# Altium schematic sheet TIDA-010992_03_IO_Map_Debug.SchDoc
size 431 x 279 mm; Date: Not shown in title block; ApprovedBy: Not shown in title block; CheckedBy: Not shown in title block; Author: Not shown in title block; CompanyName: Not shown in title block; Engineer: Not shown in title block; Organization: Not shown in title block; Address1: Not shown in title block; Address2: Not shown in title block; Address3: Not shown in title block; Address4: Not shown in title block; DocumentNumber: 3; Revision: Use project parameter SCH_Rev; SheetNumber: 3; SheetTotal: 13; PageSetup: Record=PageOptions¦CenterHorizontal=True¦CenterVertical=True¦PrintScale=1.00¦XCorrection=1.00¦YCorrection=1.00¦PrintKind=0¦BorderSize=5000000¦LeftOffset=0¦BottomOffset=0¦Orientation=2¦PaperLength=1000¦PaperWidth=1000¦Scale=100¦PaperSource=15¦PrintQuality=600¦MediaType=1¦DitherType=10¦PaperKind=Letter¦PrintScaleMode=1
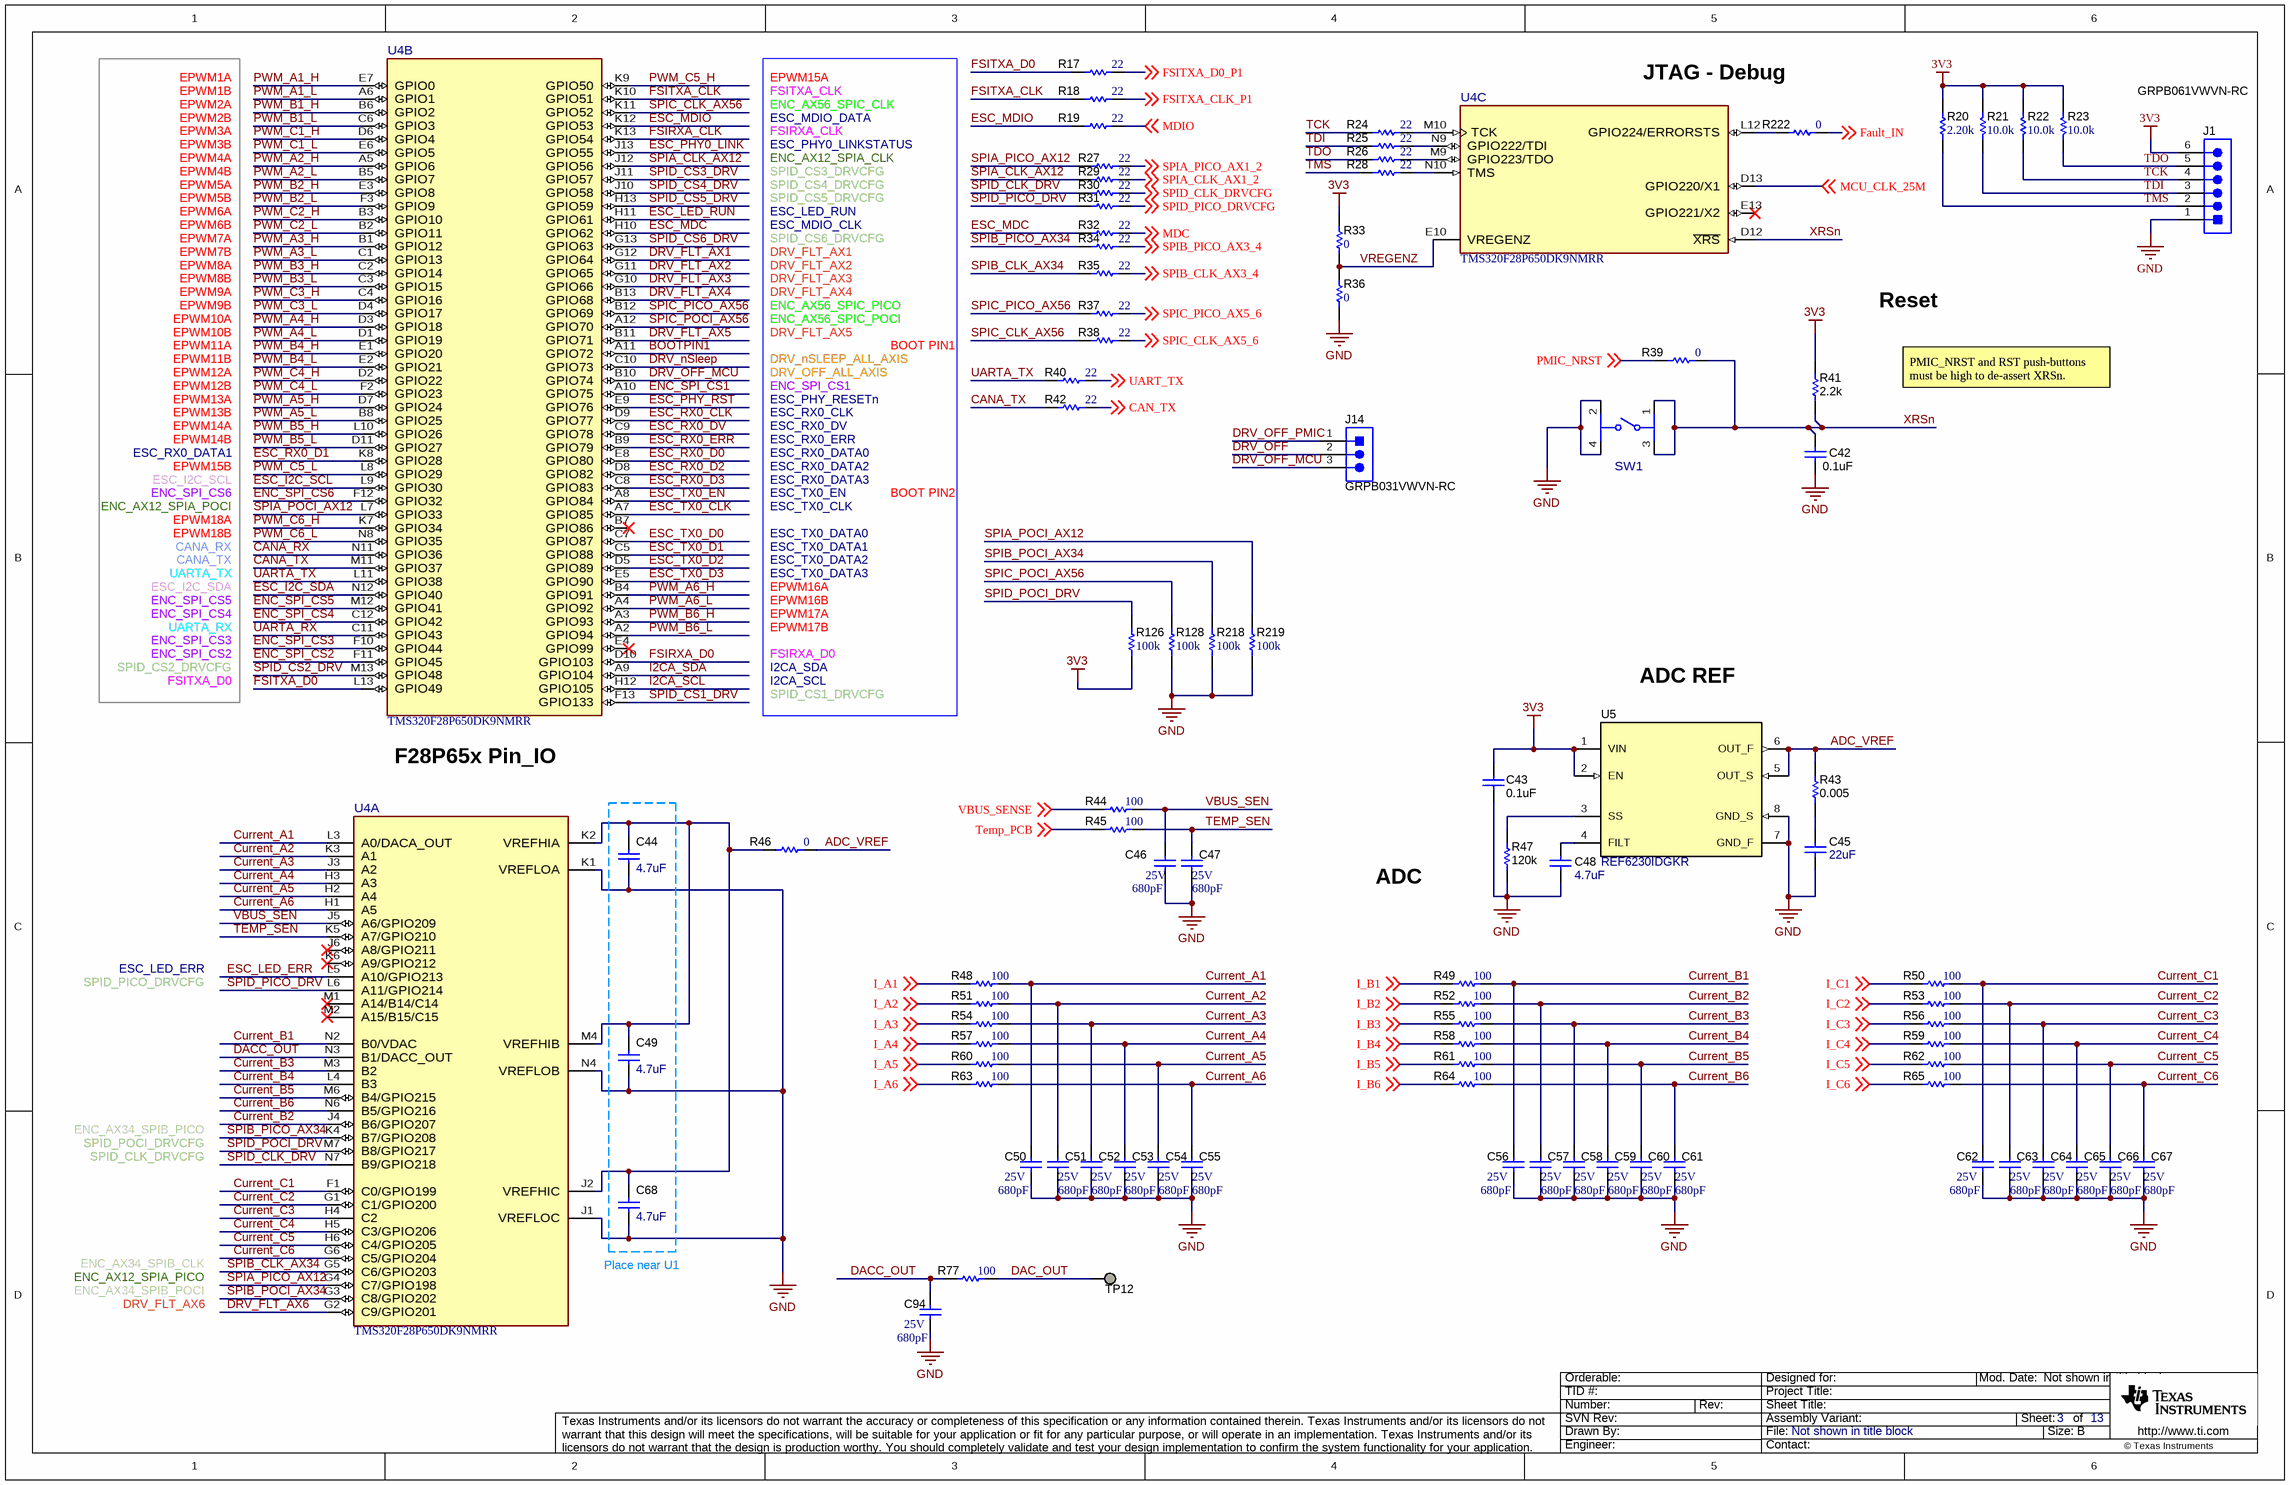
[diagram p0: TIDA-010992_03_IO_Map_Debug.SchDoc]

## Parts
C42  ValueDisplayed: 0.1uF  [0402]  (hidden comment: 885012205037)
C43  ValueDisplayed: 0.1uF  [0402]  (hidden comment: 885012205037)
C44  ValueDisplayed: 4.7uF  [0603]  (hidden comment: GRM188R61C475KAAJ)
C45  ValueDisplayed: 22uF  [0603]  (hidden comment: GRM188R61A226ME15D)
C46  VDC_V: 25V  ValueDisplayed: 680pF  [0201]  (hidden comment: GRM033R71E681KA01D)
C47  VDC_V: 25V  ValueDisplayed: 680pF  [0201]  (hidden comment: GRM033R71E681KA01D)
C48  ValueDisplayed: 4.7uF  [0603]  (hidden comment: GRM188R61C475KAAJ)
C49  ValueDisplayed: 4.7uF  [0603]  (hidden comment: GRM188R61C475KAAJ)
C50  VDC_V: 25V  ValueDisplayed: 680pF  [0201]  (hidden comment: GRM033R71E681KA01D)
C51  VDC_V: 25V  ValueDisplayed: 680pF  [0201]  (hidden comment: GRM033R71E681KA01D)
C52  VDC_V: 25V  ValueDisplayed: 680pF  [0201]  (hidden comment: GRM033R71E681KA01D)
C53  VDC_V: 25V  ValueDisplayed: 680pF  [0201]  (hidden comment: GRM033R71E681KA01D)
C54  VDC_V: 25V  ValueDisplayed: 680pF  [0201]  (hidden comment: GRM033R71E681KA01D)
C55  VDC_V: 25V  ValueDisplayed: 680pF  [0201]  (hidden comment: GRM033R71E681KA01D)
C56  VDC_V: 25V  ValueDisplayed: 680pF  [0201]  (hidden comment: GRM033R71E681KA01D)
C57  VDC_V: 25V  ValueDisplayed: 680pF  [0201]  (hidden comment: GRM033R71E681KA01D)
C58  VDC_V: 25V  ValueDisplayed: 680pF  [0201]  (hidden comment: GRM033R71E681KA01D)
C59  VDC_V: 25V  ValueDisplayed: 680pF  [0201]  (hidden comment: GRM033R71E681KA01D)
C60  VDC_V: 25V  ValueDisplayed: 680pF  [0201]  (hidden comment: GRM033R71E681KA01D)
C61  VDC_V: 25V  ValueDisplayed: 680pF  [0201]  (hidden comment: GRM033R71E681KA01D)
C62  VDC_V: 25V  ValueDisplayed: 680pF  [0201]  (hidden comment: GRM033R71E681KA01D)
C63  VDC_V: 25V  ValueDisplayed: 680pF  [0201]  (hidden comment: GRM033R71E681KA01D)
C64  VDC_V: 25V  ValueDisplayed: 680pF  [0201]  (hidden comment: GRM033R71E681KA01D)
C65  VDC_V: 25V  ValueDisplayed: 680pF  [0201]  (hidden comment: GRM033R71E681KA01D)
C66  VDC_V: 25V  ValueDisplayed: 680pF  [0201]  (hidden comment: GRM033R71E681KA01D)
C67  VDC_V: 25V  ValueDisplayed: 680pF  [0201]  (hidden comment: GRM033R71E681KA01D)
C68  ValueDisplayed: 4.7uF  [0603]  (hidden comment: GRM188R61C475KAAJ)
C94  VDC_V: 25V  ValueDisplayed: 680pF  [0201]  (hidden comment: GRM033R71E681KA01D)
J1  GRPB061VWVN-RC  [Sullins_GRPB061VWVN-RC]
J14  GRPB031VWVN-RC  [Sullins_GRPB031VWVN-RC]
R17  ValueDisplayed: 22  [0201]  (hidden comment: ERJ-1GNJ220C)
R18  ValueDisplayed: 22  [0201]  (hidden comment: ERJ-1GNJ220C)
R19  ValueDisplayed: 22  [0201]  (hidden comment: ERJ-1GNJ220C)
R20  ValueDisplayed: 2.20k  [0402]  (hidden comment: CRCW04022K20FKED)
R21  ValueDisplayed: 10.0k  [0402]  (hidden comment: ERJ-2RKF1002X)
R22  ValueDisplayed: 10.0k  [0402]  (hidden comment: ERJ-2RKF1002X)
R23  ValueDisplayed: 10.0k  [0402]  (hidden comment: ERJ-2RKF1002X)
R24  ValueDisplayed: 22  [0201]  (hidden comment: ERJ-1GNJ220C)
R25  ValueDisplayed: 22  [0201]  (hidden comment: ERJ-1GNJ220C)
R26  ValueDisplayed: 22  [0201]  (hidden comment: ERJ-1GNJ220C)
R27  ValueDisplayed: 22  [0201]  (hidden comment: ERJ-1GNJ220C)
R28  ValueDisplayed: 22  [0201]  (hidden comment: ERJ-1GNJ220C)
R29  ValueDisplayed: 22  [0201]  (hidden comment: ERJ-1GNJ220C)
R30  ValueDisplayed: 22  [0201]  (hidden comment: ERJ-1GNJ220C)
R31  ValueDisplayed: 22  [0201]  (hidden comment: ERJ-1GNJ220C)
R32  ValueDisplayed: 22  [0201]  (hidden comment: ERJ-1GNJ220C)
R33  value 0  [0402L]  (hidden comment: ERJ-2GE0R00X)
R34  ValueDisplayed: 22  [0201]  (hidden comment: ERJ-1GNJ220C)
R35  ValueDisplayed: 22  [0201]  (hidden comment: ERJ-1GNJ220C)
R36  value 0  [0402L]  (hidden comment: ERJ-2GE0R00X)
R37  ValueDisplayed: 22  [0201]  (hidden comment: ERJ-1GNJ220C)
R38  ValueDisplayed: 22  [0201]  (hidden comment: ERJ-1GNJ220C)
R39  value 0  [0402L]  (hidden comment: ERJ-2GE0R00X)
R40  ValueDisplayed: 22  [0201]  (hidden comment: ERJ-1GNJ220C)
R41  ValueDisplayed: 2.2k  [0402]  (hidden comment: CRCW04022K20JNED)
R42  ValueDisplayed: 22  [0201]  (hidden comment: ERJ-1GNJ220C)
R43  ValueDisplayed: 0.005  [0603]  (hidden comment: ERJ3LWFR005V)
R44  ValueDisplayed: 100  [0201]  (hidden comment: RC0201FR-7D100RL)
R45  ValueDisplayed: 100  [0201]  (hidden comment: RC0201FR-7D100RL)
R46  value 0  [0402L]  (hidden comment: ERJ-2GE0R00X)
R47  ValueDisplayed: 120k  [0603]  (hidden comment: RG1608P-124-B-T5)
R48  ValueDisplayed: 100  [0201]  (hidden comment: RC0201FR-7D100RL)
R49  ValueDisplayed: 100  [0201]  (hidden comment: RC0201FR-7D100RL)
R50  ValueDisplayed: 100  [0201]  (hidden comment: RC0201FR-7D100RL)
R51  ValueDisplayed: 100  [0201]  (hidden comment: RC0201FR-7D100RL)
R52  ValueDisplayed: 100  [0201]  (hidden comment: RC0201FR-7D100RL)
R53  ValueDisplayed: 100  [0201]  (hidden comment: RC0201FR-7D100RL)
R54  ValueDisplayed: 100  [0201]  (hidden comment: RC0201FR-7D100RL)
R55  ValueDisplayed: 100  [0201]  (hidden comment: RC0201FR-7D100RL)
R56  ValueDisplayed: 100  [0201]  (hidden comment: RC0201FR-7D100RL)
R57  ValueDisplayed: 100  [0201]  (hidden comment: RC0201FR-7D100RL)
R58  ValueDisplayed: 100  [0201]  (hidden comment: RC0201FR-7D100RL)
R59  ValueDisplayed: 100  [0201]  (hidden comment: RC0201FR-7D100RL)
R60  ValueDisplayed: 100  [0201]  (hidden comment: RC0201FR-7D100RL)
R61  ValueDisplayed: 100  [0201]  (hidden comment: RC0201FR-7D100RL)
R62  ValueDisplayed: 100  [0201]  (hidden comment: RC0201FR-7D100RL)
R63  ValueDisplayed: 100  [0201]  (hidden comment: RC0201FR-7D100RL)
R64  ValueDisplayed: 100  [0201]  (hidden comment: RC0201FR-7D100RL)
R65  ValueDisplayed: 100  [0201]  (hidden comment: RC0201FR-7D100RL)
R77  ValueDisplayed: 100  [0201]  (hidden comment: RC0201FR-7D100RL)
R126  ValueDisplayed: 100k  [0201]  (hidden comment: RC0201FR-07100KL)
R128  ValueDisplayed: 100k  [0201]  (hidden comment: RC0201FR-07100KL)
R218  ValueDisplayed: 100k  [0201]  (hidden comment: RC0201FR-07100KL)
R219  ValueDisplayed: 100k  [0201]  (hidden comment: RC0201FR-07100KL)
R222  value 0  [0402L]  (hidden comment: ERJ-2GE0R00X)
SW1  434351045816  [FP-434351045816_SMT_SW_4MM7_4MM5-MFG]  (value not drawn)
TP12  TESTPOINT  [TP_25MIL-SMT]  (value not drawn)  (no BOM)
U4  TMS320F28P650DK9NMRR  [NMR0169A-MFG]  (parts A,B,C of 4)
U5  REF6230IDGKR  [DGK0008A_N]

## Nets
3V3: C43.1 J1.6 R20.2 R21.1 R22.1 R23.1 R33.2 R41.2 R126.1 U5.1(VIN) U5.2(EN)
GND: C42.2 C43.2 C44.2 C45.2 C46.2 C47.2 C48.2 C49.2 C50.2 C51.2 C52.2 C53.2 C54.2 C55.2 C56.2 C57.2 C58.2 C59.2 C60.2 C61.2 C62.2 C63.2 C64.2 C65.2 C66.2 C67.2 C68.2 C94.2 J1.1 R36.1 R47.1 R128.1 R218.1 R219.1 SW1.2 SW1.4 U4.J1(VREFLOC) U4.K1(VREFLOA) U4.N4(VREFLOB) U5.7(GND_F) U5.8(GND_S)
ADC_VREF: R43.2 R46.2 U5.5(OUT_S) U5.6(OUT_F)
BOOTPIN1: U4.A11(GPIO72)
CAN_TX: R42.2 ; off-sheet CAN_TX
CANA_RX: U4.N11(GPIO36)
CANA_TX: R42.1 U4.M11(GPIO37)
Current_A1: C50.1 R48.2 U4.L3(A0/DACA_OUT)
Current_A2: C51.1 R51.2 U4.K3(A1)
Current_A3: C52.1 R54.2 U4.J3(A2)
Current_A4: C53.1 R57.2 U4.H3(A3)
Current_A5: C54.1 R60.2 U4.H2(A4)
Current_A6: C55.1 R63.2 U4.H1(A5)
Current_B1: C56.1 R49.2 U4.N2(B0/VDAC)
Current_B2: C57.1 R52.2 U4.J4(B6/GPIO207)
Current_B3: C58.1 R55.2 U4.M3(B2)
Current_B4: C59.1 R58.2 U4.L4(B3)
Current_B5: C60.1 R61.2 U4.M6(B4/GPIO215)
Current_B6: C61.1 R64.2 U4.N6(B5/GPIO216)
Current_C1: C62.1 R50.2 U4.F1(C0/GPIO199)
Current_C2: C63.1 R53.2 U4.G1(C1/GPIO200)
Current_C3: C64.1 R56.2 U4.H4(C2)
Current_C4: C65.1 R59.2 U4.H5(C3/GPIO206)
Current_C5: C66.1 R62.2 U4.H6(C4/GPIO205)
Current_C6: C67.1 R65.2 U4.G6(C5/GPIO204)
DAC_OUT: R77.2 TP12.1
DACC_OUT: C94.1 R77.1 U4.N3(B1/DACC_OUT)
DRV_FLT_AX1: U4.G12(GPIO64)
DRV_FLT_AX2: U4.G11(GPIO65)
DRV_FLT_AX3: U4.G10(GPIO66)
DRV_FLT_AX4: U4.B13(GPIO68)
DRV_FLT_AX5: U4.B11(GPIO71)
DRV_FLT_AX6: U4.G2(C9/GPIO201)
DRV_nSleep: U4.C10(GPIO73)
DRV_OFF: J14.2
DRV_OFF_MCU: J14.3 U4.B10(GPIO74)
DRV_OFF_PMIC: J14.1
ENC_SPI_CS1: U4.A10(GPIO75)
ENC_SPI_CS2: U4.F11(GPIO45)
ENC_SPI_CS3: U4.F10(GPIO44)
ENC_SPI_CS4: U4.C12(GPIO42)
ENC_SPI_CS5: U4.M12(GPIO41)
ENC_SPI_CS6: U4.F12(GPIO32)
ESC_I2C_SCL: U4.L9(GPIO30)
ESC_I2C_SDA: U4.N12(GPIO40)
ESC_LED_ERR: U4.L5(A10/GPIO213)
ESC_LED_RUN: U4.H11(GPIO61)
ESC_MDC: R32.1 U4.H10(GPIO62)
ESC_MDIO: R19.1 U4.K12(GPIO53)
ESC_PHY0_LINK: U4.J13(GPIO55)
ESC_PHY_RST: U4.E9(GPIO76)
ESC_RX0_CLK: U4.D9(GPIO77)
ESC_RX0_D0: U4.E8(GPIO80)
ESC_RX0_D1: U4.K8(GPIO28)
ESC_RX0_D2: U4.D8(GPIO82)
ESC_RX0_D3: U4.C8(GPIO83)
ESC_RX0_DV: U4.C9(GPIO78)
ESC_RX0_ERR: U4.B9(GPIO79)
ESC_TX0_CLK: U4.A7(GPIO85)
ESC_TX0_D0: U4.C7(GPIO87)
ESC_TX0_D1: U4.C5(GPIO88)
ESC_TX0_D2: U4.D5(GPIO89)
ESC_TX0_D3: U4.E5(GPIO90)
ESC_TX0_EN: U4.A8(GPIO84)
Fault_IN: R222.2 ; off-sheet Fault_IN
FSIRXA_CLK: U4.K13(GPIO54)
FSIRXA_D0: U4.D10(GPIO103)
FSITXA_CLK: R18.1 U4.K10(GPIO51)
FSITXA_CLK_P1: R18.2 ; off-sheet FSITXA_CLK_P1
FSITXA_D0: R17.1 U4.L13(GPIO49)
FSITXA_D0_P1: R17.2 ; off-sheet FSITXA_D0_P1
I2CA_SCL: U4.H12(GPIO105)
I2CA_SDA: U4.A9(GPIO104)
I_A1: R48.1 ; off-sheet I_A1
I_A2: R51.1 ; off-sheet I_A2
I_A3: R54.1 ; off-sheet I_A3
I_A4: R57.1 ; off-sheet I_A4
I_A5: R60.1 ; off-sheet I_A5
I_A6: R63.1 ; off-sheet I_A6
I_B1: R49.1 ; off-sheet I_B1
I_B2: R52.1 ; off-sheet I_B2
I_B3: R55.1 ; off-sheet I_B3
I_B4: R58.1 ; off-sheet I_B4
I_B5: R61.1 ; off-sheet I_B5
I_B6: R64.1 ; off-sheet I_B6
I_C1: R50.1 ; off-sheet I_C1
I_C2: R53.1 ; off-sheet I_C2
I_C3: R56.1 ; off-sheet I_C3
I_C4: R59.1 ; off-sheet I_C4
I_C5: R62.1 ; off-sheet I_C5
I_C6: R65.1 ; off-sheet I_C6
MCU_CLK_25M: U4.D13(GPIO220/X1) ; off-sheet MCU_CLK_25M
MDC: R32.2 ; off-sheet MDC
MDIO: R19.2 ; off-sheet MDIO
PMIC_NRST: R39.1 ; off-sheet PMIC_NRST
PWM_A1_H: U4.E7(GPIO0)
PWM_A1_L: U4.A6(GPIO1)
PWM_A2_H: U4.A5(GPIO6)
PWM_A2_L: U4.B5(GPIO7)
PWM_A3_H: U4.B1(GPIO12)
PWM_A3_L: U4.C1(GPIO13)
PWM_A4_H: U4.D3(GPIO18)
PWM_A4_L: U4.D1(GPIO19)
PWM_A5_H: U4.D7(GPIO24)
PWM_A5_L: U4.B8(GPIO25)
PWM_A6_H: U4.B4(GPIO91)
PWM_A6_L: U4.A4(GPIO92)
PWM_B1_H: U4.B6(GPIO2)
PWM_B1_L: U4.C6(GPIO3)
PWM_B2_H: U4.E3(GPIO8)
PWM_B2_L: U4.F3(GPIO9)
PWM_B3_H: U4.C2(GPIO14)
PWM_B3_L: U4.C3(GPIO15)
PWM_B4_H: U4.E1(GPIO20)
PWM_B4_L: U4.E2(GPIO21)
PWM_B5_H: U4.L10(GPIO26)
PWM_B5_L: U4.D11(GPIO27)
PWM_B6_H: U4.A3(GPIO93)
PWM_B6_L: U4.A2(GPIO94)
PWM_C1_H: U4.D6(GPIO4)
PWM_C1_L: U4.E6(GPIO5)
PWM_C2_H: U4.B3(GPIO10)
PWM_C2_L: U4.B2(GPIO11)
PWM_C3_H: U4.C4(GPIO16)
PWM_C3_L: U4.D4(GPIO17)
PWM_C4_H: U4.D2(GPIO22)
PWM_C4_L: U4.F2(GPIO23)
PWM_C5_H: U4.K9(GPIO50)
PWM_C5_L: U4.L8(GPIO29)
PWM_C6_H: U4.K7(GPIO34)
PWM_C6_L: U4.N8(GPIO35)
SPIA_CLK_AX1_2: R29.2 ; off-sheet SPIA_CLK_AX1_2
SPIA_CLK_AX12: R29.1 U4.J12(GPIO56)
SPIA_PICO_AX1_2: R27.2 ; off-sheet SPIA_PICO_AX1_2
SPIA_PICO_AX12: R27.1 U4.G4(C7/GPIO198)
SPIA_POCI_AX12: R219.2 U4.L7(GPIO33)
SPIB_CLK_AX3_4: R35.2 ; off-sheet SPIB_CLK_AX3_4
SPIB_CLK_AX34: R35.1 U4.G5(C6/GPIO203)
SPIB_PICO_AX3_4: R34.2 ; off-sheet SPIB_PICO_AX3_4
SPIB_PICO_AX34: R34.1 U4.K4(B7/GPIO208)
SPIB_POCI_AX34: R218.2 U4.G3(C8/GPIO202)
SPIC_CLK_AX5_6: R38.2 ; off-sheet SPIC_CLK_AX5_6
SPIC_CLK_AX56: R38.1 U4.K11(GPIO52)
SPIC_PICO_AX5_6: R37.2 ; off-sheet SPIC_PICO_AX5_6
SPIC_PICO_AX56: R37.1 U4.B12(GPIO69)
SPIC_POCI_AX56: R128.2 U4.A12(GPIO70)
SPID_CLK_DRV: R30.1 U4.N7(B9/GPIO218)
SPID_CLK_DRVCFG: R30.2 ; off-sheet SPID_CLK_DRVCFG
SPID_CS1_DRV: U4.F13(GPIO133)
SPID_CS2_DRV: U4.M13(GPIO48)
SPID_CS3_DRV: U4.J11(GPIO57)
SPID_CS4_DRV: U4.J10(GPIO58)
SPID_CS5_DRV: U4.H13(GPIO59)
SPID_CS6_DRV: U4.G13(GPIO63)
SPID_PICO_DRV: R31.1 U4.L6(A11/GPIO214)
SPID_PICO_DRVCFG: R31.2 ; off-sheet SPID_PICO_DRVCFG
SPID_POCI_DRV: R126.2 U4.M7(B8/GPIO217)
TCK: J1.4 R22.2 R24.1
TDI: J1.3 R21.2 R25.1
TDO: J1.5 R23.2 R26.1
Temp_PCB: R45.1 ; off-sheet Temp_PCB
TEMP_SEN: C47.1 R45.2 U4.K5(A7/GPIO210)
TMS: J1.2 R20.1 R28.1
UART_TX: R40.2 ; off-sheet UART_TX
UARTA_RX: U4.C11(GPIO43)
UARTA_TX: R40.1 U4.L11(GPIO38)
VBUS_SEN: C46.1 R44.2 U4.J5(A6/GPIO209)
VBUS_SENSE: R44.1 ; off-sheet VBUS_SENSE
VREGENZ: R33.1 R36.2 U4.E10(VREGENZ)
XRSn: C42.1 R39.2 R41.1 SW1.1 SW1.3 U4.D12(~{XRS})
NetC44_1: C44.1 C49.1 C68.1 R46.1 U4.J2(VREFHIC) U4.K2(VREFHIA) U4.M4(VREFHIB)
NetC45_1: C45.1 R43.1
NetC48_1: C48.1 U5.4(FILT)
NetR24_2: R24.2 U4.M10(TCK)
NetR25_2: R25.2 U4.N9(GPIO222/TDI)
NetR26_2: R26.2 U4.M9(GPIO223/TDO)
NetR28_2: R28.2 U4.N10(TMS)
NetR47_2: R47.2 U5.3(SS)
NetR222_1: R222.1 U4.L12(GPIO224/ERRORSTS)

Not connected (* = marked no-connect by the designer): U4 B7(GPIO86)* E4(GPIO99)* E13(GPIO221/X2)* J6(A8/GPIO211)* K6(A9/GPIO212)* M1(A14/B14/C14)* M2(A15/B15/C15)*

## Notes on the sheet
- EPWM1A
- EPWM1B
- FSITXA_CLK
- EPWM15A
- JTAG - Debug
- EPWM4A
- EPWM2A
- EPWM2B
- EPWM3A
- EPWM3B
- FSIRXA_CLK
- ESC_MDIO_DATA
- ESC_PHY0_LINKSTATUS
- ENC_AX56_SPIC_CLK
- ENC_AX12_SPIA_CLK
- EPWM5A
- EPWM5B
- EPWM4B
- EPWM6A
- EPWM6B
- ESC_LED_RUN
- ESC_MDIO_CLK
- SPID_CS3_DRVCFG
- SPID_CS5_DRVCFG
- SPID_CS4_DRVCFG
- EPWM7A
- EPWM7B
- EPWM8A
- EPWM8B
- EPWM9A
- SPID_CS6_DRVCFG
- DRV_FLT_AX1
- DRV_FLT_AX2
- DRV_FLT_AX3
- DRV_FLT_AX4
- Reset
- EPWM9B
- EPWM10A
- EPWM10B
- EPWM11A
- EPWM11B
- ENC_AX56_SPIC_PICO
- ENC_AX56_SPIC_POCI
- DRV_FLT_AX5
- DRV_nSLEEP_ALL_AXIS
- BOOT PIN1
- EPWM12A
- EPWM12B
- EPWM13A
- EPWM13B
- EPWM14A
- ESC_PHY_RESETn
- ESC_RX0_CLK
- ESC_RX0_DV
- ENC_SPI_CS1
- DRV_OFF_ALL_AXIS
- PMIC_NRST and RST push-buttons must be high to de-assert XRSn.
- ESC_RX0_DATA1
- EPWM14B
- EPWM15B
- ENC_SPI_CS6
- ESC_I2C_SCL
- ESC_RX0_DATA0
- ESC_RX0_DATA2
- ESC_RX0_DATA3
- ESC_RX0_ERR
- ESC_TX0_EN
- BOOT PIN2
- ENC_AX12_SPIA_POCI
- CANA_RX
- CANA_TX
- EPWM18A
- EPWM18B
- ESC_TX0_CLK
- ESC_TX0_DATA0
- ESC_TX0_DATA1
- ESC_TX0_DATA2
- UARTA_RX
- UARTA_TX
- ENC_SPI_CS4
- ENC_SPI_CS5
- ESC_I2C_SDA
- ESC_TX0_DATA3
- EPWM16A
- EPWM16B
- EPWM17A
- EPWM17B
- FSITXA_D0
- ENC_SPI_CS2
- SPID_CS2_DRVCFG
- ENC_SPI_CS3
- I2CA_SCL
- FSIRXA_D0
- SPID_CS1_DRVCFG
- I2CA_SDA
- ADC REF
- (near U4) F28P65x Pin_IO
- ADC
- ESC_LED_ERR
- SPID_PICO_DRVCFG
- ENC_AX34_SPIB_PICO
- SPID_CLK_DRVCFG
- SPID_POCI_DRVCFG
- ENC_AX12_SPIA_PICO
- ENC_AX34_SPIB_CLK
- ENC_AX34_SPIB_POCI
- Place near U1
- DRV_FLT_AX6

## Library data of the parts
C42 C43 = CMP-0006228-2: CAP, CERM, 0.1 uF, 16 V, +/- 10%, X7R, 0402; Manufacturer: Wurth Elektronik; TaMin_C: -55°C; Polarized: N; SizeAreaWB_mm2: 3; Value1: Unknown; U/M: EA; Value: 0.1uF; TaMax_C: 125°C; SizeZ_mm: 0.6; SizeX_mm: 1; SizeY_mm: 0.5; Value2: 16V; Cap_F: 100nF; AEC Category: Q200
C44 C48 C49 C68 = CMP-0007341-4: CAP, CERM, 4.7 uF, 16 V, +/- 10%, X5R, 0603; Manufacturer: MuRata; TaMin_C: -55°C; Polarized: N; SizeAreaWB_mm2: 4.68; Value1: Unknown; U/M: EA; Value: 4.7uF; TaMax_C: 85°C; SizeZ_mm: 1; SizeX_mm: 1.6; SizeY_mm: 0.8; Value2: 16V; SizeArea_mm2: 1.28; Cap_F: 4.7µF; AEC Category: Q200
C45 = CMP-0007324-5: CAP, CERM, 22 uF, 10 V, +/- 20%, X5R, 0603; Manufacturer: MuRata; TaMin_C: -55°C; Polarized: N; SizeAreaWB_mm2: 4.68; Value1: Unknown; U/M: EA; Value: 22uF; TaMax_C: 85°C; SizeZ_mm: 1; SizeX_mm: 1.6; SizeY_mm: 0.8; Value2: 10V; SizeArea_mm2: 1.28; Cap_F: 22µF; AEC Category: Q200
C46 C47 C50-C67 C94 = CMP-0009776-1: CAP, CERM, 680 pF, 25 V, +/- 10%, X7R, 0201; Manufacturer: MuRata; TaMin_C: -55°C; Polarized: N; SizeAreaWB_mm2: 2.08; Value1: Unknown; U/M: EA; Value: 680pF; TaMax_C: 125°C; SizeZ_mm: 0.26; SizeX_mm: 0.6; SizeY_mm: 0.3; SizeArea_mm2: 0.18; AEC Category: Q200
J1 = CMP-0054561-1: Header, 50mil, 6x1, Gold,  TH; Manufacturer: Sullins Connector Solutions; CT: FALSE; CNHeader: TRUE
J14 = CMP-0054564-1: Header, 50mil, 3x1, Gold, TH; Manufacturer: Sullins Connector Solutions; CNHeader: TRUE; Green_Lifecycle: Not Set; Shrouded: N; Gender: Male; Green_REACh: Incomplete; Row_Count: 1; CT: FALSE
R17-R19 R24-R32 R34 R35 R37 R38 R40 R42 = CMP-0027015-3: RES, 22, 5%, 0.05 W, AEC-Q200 Grade 1, 0201; Manufacturer: Panasonic; Power_W: 50mW; TempCo: 200 ppm/C; Value_Code: 22R0; U/M: EA; Value: 22; EIA_Code: E24; SizeX_mm: 0.6; SizeY_mm: 0.3; SizeZ_mm: 0.26; Value2: 0.05W; SizeArea_mm2: 0.18; AEC Qualified: Y; AEC Grade: 1; AEC Category: Q200
R20 = CMP-0026231-2: RES, 2.20 k, 1%, 0.063 W, AEC-Q200 Grade 0, 0402; Manufacturer: Vishay-Dale; Power_W: 63mW; TempCo: 100 ppm/C; Value_Code: 2k20; Value: 2.20k; Res_ohm: 2.2k; SizeX_mm: 1; SizeY_mm: 0.5; SizeZ_mm: 0.6; Value2: 0.063W; AEC Qualified: Y; AEC Category: Q200; AEC Grade: 0
R21-R23 = CMP-0026658-1: RES, 10.0 k, 1%, 0.1 W, 0402; Manufacturer: Panasonic; Power_W: 100mW; TempCo: 100 ppm/C; Value_Code: 10k0; U/M: EA; Value: 10.0k; EIA_Code: E96; Res_ohm: 10k; SizeX_mm: 1; SizeY_mm: 0.5; SizeZ_mm: 0.6; Value2: 0.1W; VDC_V: 50V; AEC Category: Q200
R33 R36 R39 R46 R222 = CMP-0026992-3: RES, 0, 5%, 0.1 W, AEC-Q200 Grade 0, 0402; Manufacturer: Panasonic; Power_W: 100mW; TempCo: 600 ppm/C; Value_Code: 0000; EIA_Code: E24; SizeX_mm: 1; SizeY_mm: 0.5; SizeZ_mm: 0.6; Value2: 0.1W; AEC Qualified: Y; VDC_V: 50V; AEC Category: Q200; SizeAreaWB_mm2: 3
R41 = CMP-0026890-5: RES, 2.2 k, 5%, 0.063 W, AEC-Q200 Grade 0, 0402; Manufacturer: Vishay-Dale; Value: 2.2k; Value_Code: 2k20; Power_W: 63mW; Value2: 0.063W; VDC_V: 50V; TempCo: 200 ppm/C; SizeArea_mm2: 0.5; SizeX_mm: 1; SizeZ_mm: 0.6; EIA_Code: E24; AEC Category: Q200; AEC Qualified: Y; AEC Grade: 0
R43 = CMP-0022710-2: RES, 0.005, 1%, 0.25 W, AEC-Q200 Grade 1, 0603; Manufacturer: Panasonic; Power_W: 250mW; TempCo: ppm/C; Value_Code: 5L000; U/M: EA; Value: 0.005; EIA_Code: E96; Res_ohm: 5m; SizeX_mm: 1.6; SizeY_mm: 0.8; SizeZ_mm: 1; Value2: 0.25W; SizeArea_mm2: 1.28; AEC Qualified: Y; AEC Category: Q200
R44 R45 R48-R65 R77 = CMP-0027944-1: RES, 100, 1%, 0.05 W, 0201; Manufacturer: Yageo America; Power_W: 50mW; TempCo: 200 ppm/C; Value_Code: 100R; U/M: EA; Value: 100; EIA_Code: E96; SizeX_mm: 0.6; SizeY_mm: 0.3; SizeZ_mm: 0.26; Value2: 0.05W; SizeArea_mm2: 0.18; AEC Qualified: N; VDC_V: 25V; AEC Category: Q200
R47 = CMP-0023427-3: RES, 120 k, 0.1%, 0.1 W, 0603; Manufacturer: Susumu Co Ltd; Power_W: 100mW; TempCo: 25 ppm/C; U/M: EA; Value: 120k; EIA_Code: E192; SizeX_mm: 1.6; SizeY_mm: 0.8; SizeZ_mm: 1; Value2: 0.1W; SizeArea_mm2: 1.28; VDC_V: 75V; AEC Category: Q200
R126 R128 R218 R219 = CMP-0027293-2: RES, 100 k, 1%, 0.05 W, 0201; Manufacturer: Yageo America; Power_W: 50mW; TempCo: 200 ppm/C; U/M: EA; Value: 100k; EIA_Code: E96; SizeX_mm: 0.6; SizeY_mm: 0.3; SizeZ_mm: 0.26; Value2: 0.05W; SizeArea_mm2: 0.18; AEC Qualified: N; VDC_V: 25V; AEC Category: Q200
SW1 = CMP-0093456-1: Tactile Switch SPST-NO Side Actuated Surface Mount, Right Angle; Manufacturer: Wurth Electronics; Operating Force: 160gf; SizeZ_mm: 1.75mm; AEC Qualified: No; Electromechanical Life: 200000Cycles; VDC_V: 12V; Contact Current Rating: 50mA; Coil Resistance_ohm: 100mΩ
TP12 = CMP-0078143-3: TEST POINT.  No entry in BOM.
U4 = CMP-0098413-1: Real-Time Microcontroller, NFBGA169; Manufacturer: Texas Instruments; SizeZ_mm: 1mm; AEC Qualified: No; Core Architecture: C28x; Data Bus Width: 32bits; Frequency_Fixed: 200MHz; Interface: I2C,SPI,UART,CAN,USB,LIN,SCI,Ethernet; Max Supply Voltage: 3.63V; Memory Size: 1.28MBytes; Memory Type: FLASH; Min Supply Voltage: 1.14V; Number Of A/D Converters: 3; Number Of Adc Channels: 34; Number Of Cores: 2; Number Of Ethernet Channels: 1; Number Of I/Os: 119; Number Of Pwm Channels: 36; Number Of Spi Channels: 4; Number Of Timers/Counters: 6; Ram Size: 248KBytes; Standoff Height: 0.19mm; TaMax_C: +125°C; TaMin_C: -40°C; TJmax_C: +155°C
U5 = CMP-0077709-1: High-Precision Voltage Reference with Integrated High-Bandwidth Buffer, DGK0008A (VSSOP-8); Alternate PartNumber: REF6230IDGKT; Alternate Manufacturer: Texas Instruments; SizeAreaWB_mm2: 35.955; SizeZ_mm: 1.1; SizeX_mm: 5.05; SizeY_mm: 3.1; SizeArea_mm2: 15.655; CompType: IC; AEC Qualified: N; AEC Category: Q200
